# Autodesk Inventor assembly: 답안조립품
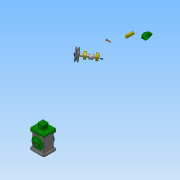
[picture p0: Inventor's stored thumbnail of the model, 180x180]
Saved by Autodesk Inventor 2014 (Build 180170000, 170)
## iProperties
Created: 2017-08
Part Number: 답안조립품
Document SubType Name: Assembly
Designer: oa51
Author: oa51
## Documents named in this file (18)
- C:\Users\oa51\Desktop\470808V1020\답안조립품.iam
- C:\Users\oa51\Desktop\470808V1020\본체.ipt
- C:\Users\oa51\Desktop\470808V1020\E-링.ipt
- C:\Users\oa51\Desktop\470808V1020\V-벨트풀리.ipt
- C:\Users\oa51\Desktop\470808V1020\덮개.ipt
- C:\Users\oa51\Desktop\470808V1020\뒤커버.ipt
- C:\Users\oa51\Desktop\470808V1020\링크.ipt
- C:\Users\oa51\Desktop\470808V1020\베어링 17 x 40 x 12.ipt
- C:\Users\oa51\Desktop\470808V1020\볼트 M4 x 8.ipt
- C:\Users\oa51\Desktop\470808V1020\볼트 M4 x 10.ipt
- C:\Users\oa51\Desktop\470808V1020\슬라이더.ipt
- C:\Users\oa51\Desktop\470808V1020\앞커버.ipt
- C:\Users\oa51\Desktop\470808V1020\오일 실 17 30 8.ipt
- C:\Users\oa51\Desktop\470808V1020\와셔 4x16.ipt
- C:\Users\oa51\Desktop\470808V1020\클레비스 핀 6 x 22.ipt
- 클레비스 핀 6 x 22.ipt
- C:\Users\oa51\Desktop\470808V1020\키 4 x 4 x 12.ipt
- C:\Users\oa51\Desktop\470808V1020\편심축.ipt
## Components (2 placed, 2 different names)
1. E-링:1
2. V-벨트풀리:1 — 각도:2
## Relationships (1: Angle 1)
- 각도:2 [Angle]: V-벨트풀리:1
